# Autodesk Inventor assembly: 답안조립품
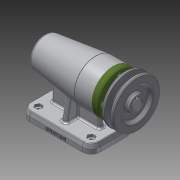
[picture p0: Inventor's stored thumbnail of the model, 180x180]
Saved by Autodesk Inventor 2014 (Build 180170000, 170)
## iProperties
Created: 2017-01
Part Number: 답안조립품
Document SubType Name: Assembly
Designer: owner
Author: owner
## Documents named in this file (12)
- C:\Users\owner\Desktop\470107V1005\답안조립품.iam
- C:\Users\owner\Desktop\470107V1005\1 본체.ipt
- C:\Users\owner\Desktop\470107V1005\V벨트풀리.ipt
- C:\Users\owner\Desktop\470107V1005\멈춤나사 M3x8.ipt
- C:\Users\owner\Desktop\470107V1005\베어링 6004.ipt
- C:\Users\owner\Desktop\470107V1005\베어링 51202.ipt
- C:\Users\owner\Desktop\470107V1005\볼트 M4 x 12.ipt
- C:\Users\owner\Desktop\470107V1005\어댑터슬리브.ipt
- C:\Users\owner\Desktop\470107V1005\오일 실.ipt
- C:\Users\owner\Desktop\470107V1005\축.ipt
- C:\Users\owner\Desktop\470107V1005\커버.ipt
- C:\Users\owner\Desktop\470107V1005\키 5 x 5 x 16.ipt
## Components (7 placed, 3 different names)
1. 1 본체:1
2. V벨트풀리:1 — 각도:3, 각도:4
3. ISO 4762 M4 x 12:1 — 각도:2
4. ISO 4762 M4 x 12:2
5. ISO 4762 M4 x 12:3
6. ISO 4762 M4 x 12:4
7. ISO 4762 M4 x 12:5
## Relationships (3: Angle 3)
- 각도:2 [Angle]: ISO 4762 M4 x 12:1
- 각도:3 [Angle]: V벨트풀리:1
- 각도:4 [Angle]: V벨트풀리:1
